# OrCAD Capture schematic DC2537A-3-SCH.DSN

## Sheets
1 PAGE2: size Custom; title: HIGH EFFICIENCY 4 PHASE 120A; rev: 3; company: TM
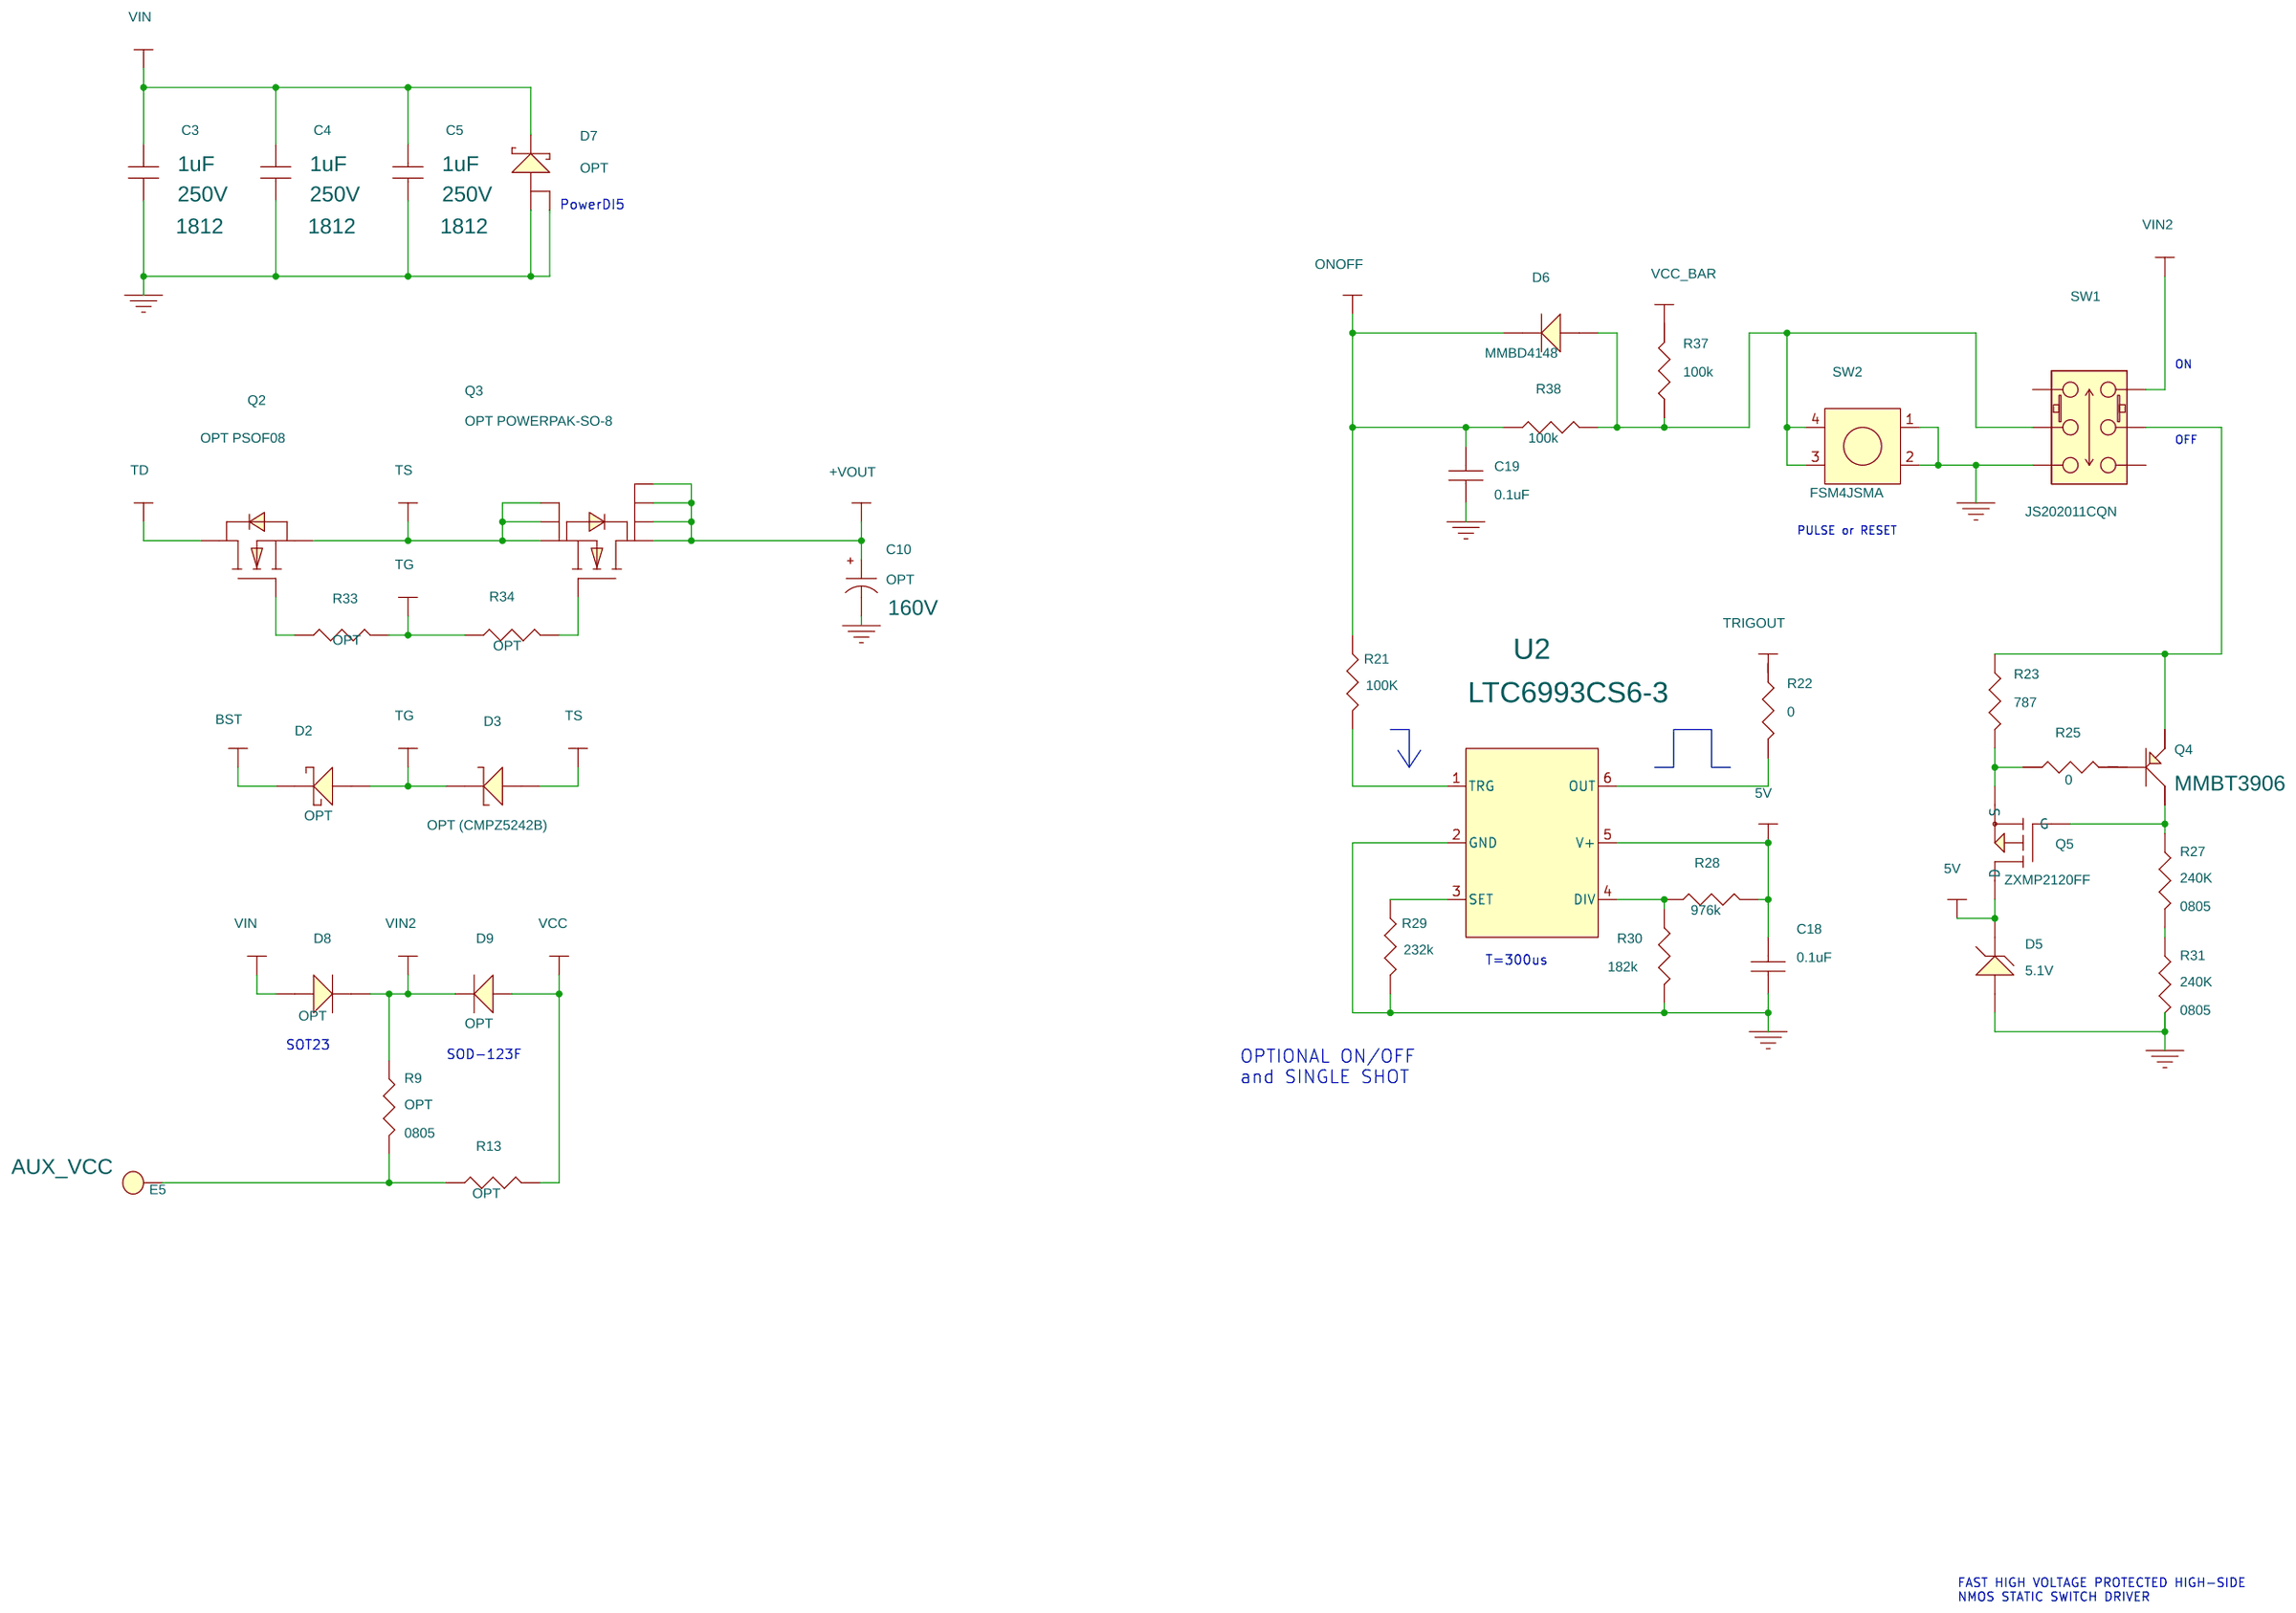
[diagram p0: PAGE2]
2 PAGE1: size Custom
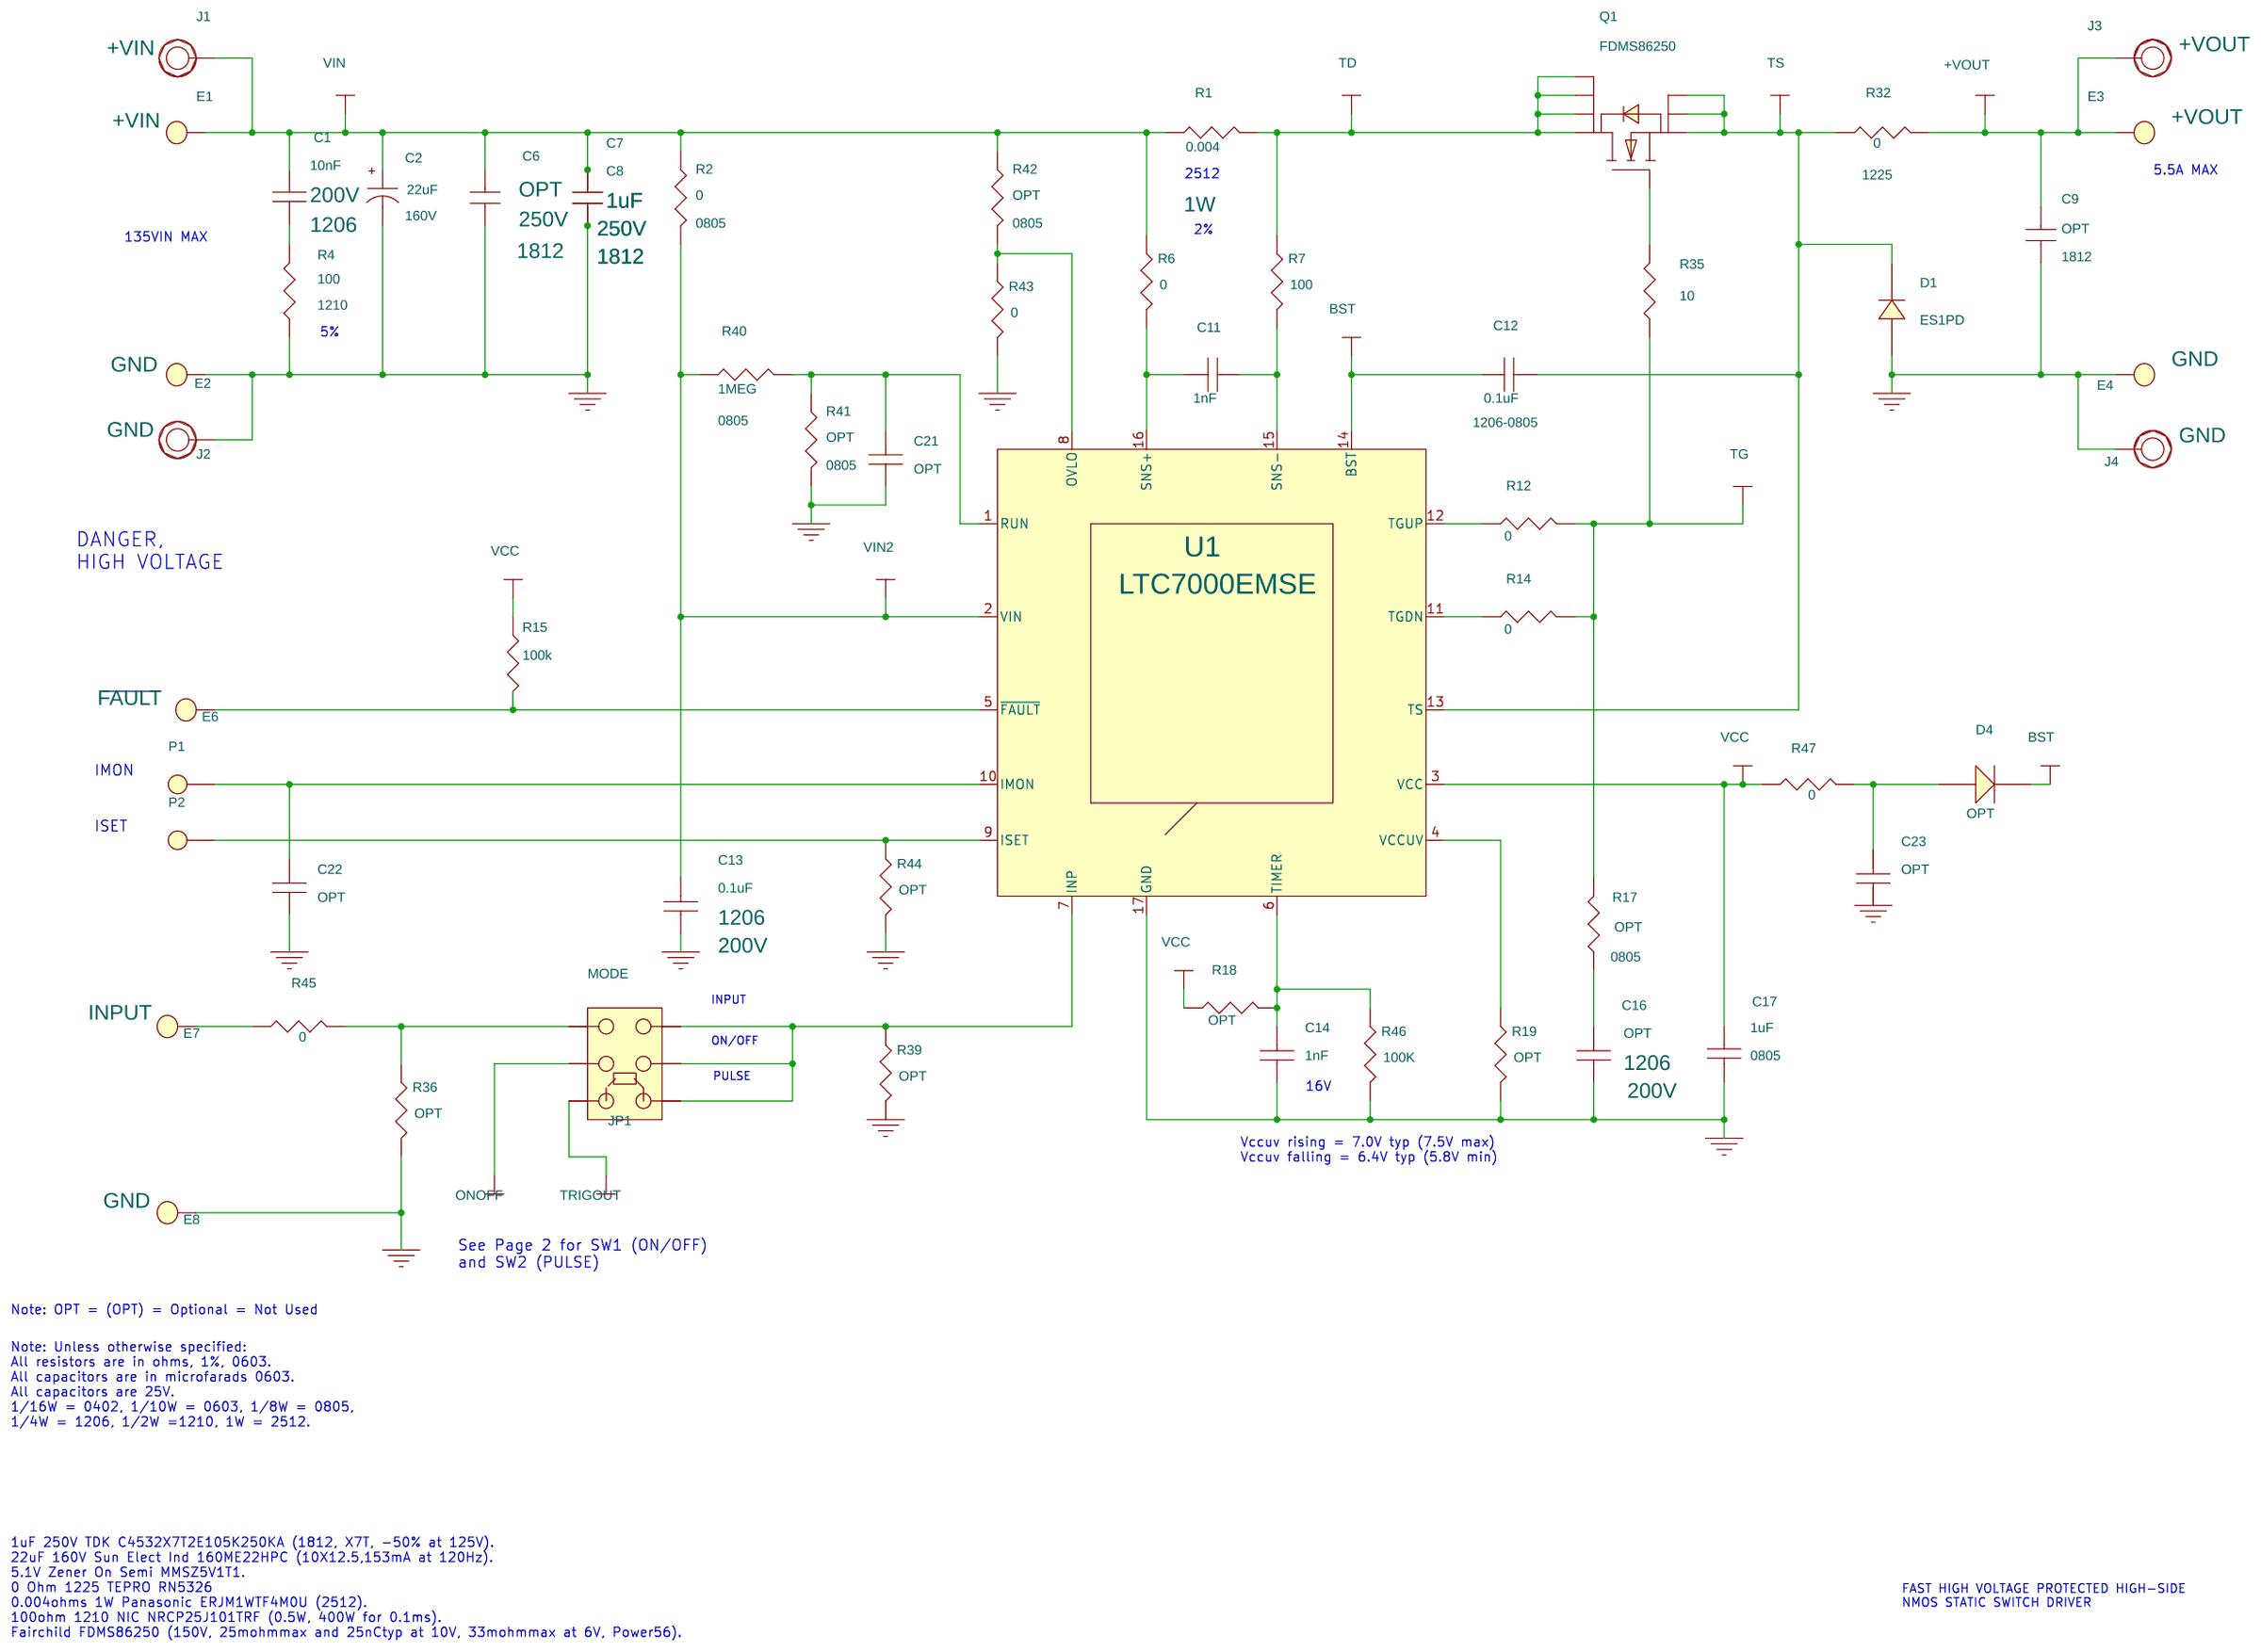
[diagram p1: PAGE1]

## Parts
sheet PAGE1
C1  10nF  [1206]
C2  22uF  [CAP-TH-EE-A-10D]
C6  OPT  [1812]
C7  1uF  [1812]
C8  1uF  [1812]
C9  OPT  [1812]
C11  1nF  [0603]
C12  0.1uF  [1206-0805]
C13  0.1uF  [1206]
C14  1nF  [0603]
C16  OPT  [1206]
C17  1uF  [0805]
C21  OPT  [0603]
C22  OPT  [0603]
C23  OPT  [0603]
D1  ES1PD  [DO-220AA]
D4  OPT  [SOT23]
E1  TURRET  [PAD150-094]
E2  TURRET  [PAD150-094]
E3  TURRET  [PAD150-094]
E4  TURRET  [PAD150-094]
E6  TURRET  [PAD150-094]
E7  TURRET  [PAD150-094]
E8  TURRET  [PAD150-094]
J1  Banana Jack  [KEYSTONE-575-4]
J2  Banana Jack  [KEYSTONE-575-4]
J3  Banana Jack  [KEYSTONE-575-4]
J4  Banana Jack  [KEYSTONE-575-4]
JP1  MODE  [HD2X3-079]
P1  TESTPAD  [PAD060-035]
P2  TESTPAD  [PAD060-035]
Q1  FDMS86250  [POWERPAK-SO-8]
R1  0.004  [2512T]
R2  0  [0805]
R4  100  [1210]
R6  0  [0603]
R7  100  [0603]
R12  0  [0603]
R14  0  [0603]
R15  100k  [0603]
R17  OPT  [0805]
R18  OPT  [0603]
R19  OPT  [0603]
R32  0  [1225]
R35  10  [0603]
R36  OPT  [0603]
R39  OPT  [0603]
R40  1MEG  [0805]
R41  OPT  [0805]
R42  OPT  [0805]
R43  0  [0603]
R44  OPT  [0603]
R45  0  [0603]
R46  100K  [0603]
R47  0  [0603]
U1  LTC7000EMSE  [MSE16]
XJP1  2mm Ctrs.
sheet PAGE2
C3  1uF  [1812]
C4  1uF  [1812]
C5  1uF  [1812]
C10  OPT  [C-10X10.5]
C18  0.1uF  [0603]
C19  0.1uF  [0603]
D2  OPT  [SOT23]
D3  OPT (CMPZ5242B)  [SOT23]
D5  MMSZ5V1T1  [SOD-123]
D6  MMBD4148  [SOT23]
D7  OPT  [POWERDI5]
D8  OPT  [SOT23]
D9  OPT  [SOD-123F]
E5  TURRET  [PAD150-094]
Q2  OPT PSOF08  [PWR-PSOF08A-3P]
Q3  OPT POWERPAK-SO-8  [POWERPAK-SO-8]
Q4  MMBT3906  [SOT23B]
Q5  ZXMP2120FF  [SOT23A]
R9  OPT  [0805]
R13  OPT  [0603]
R21  100K  [0603]
R22  0  [0603]
R23  787  [0603]
R25  0  [0603]
R27  240K  [0805]
R28  976k  [0603]
R29  232k  [0603]
R30  182k  [0603]
R31  240K  [0805]
R33  OPT  [0603]
R34  OPT  [0603]
R37  100k  [0603]
R38  100k  [0603]
SW1  JS202011CQN  [JS202011]
SW2  FSM4JSMA  [SW-FSMJSMA]
U2  LTC6993CS6-3  [TSOT23-6]

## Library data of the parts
C1 C16 = 12061C104KAT2A_0: 1ST PART FIELD: 200V; 2ND PART FIELD: 10%, 0206; 3RD PART FIELD: X7R; 4TH PART FIELD: AVX; 7TH PART FIELD: CAP.
C2 = CAP-HVH-10X10.5: 1ST PART FIELD: 160V; 5TH PART FIELD: 10X20
C3-C6 = CAP1210: 1ST PART FIELD: 250V; 2ND PART FIELD: 20%, 1210; 3RD PART FIELD: X7R; 4TH PART FIELD: TDK; 5TH PART FIELD: 1210; 7TH PART FIELD: CAP.
C7 C8 = CAP1210: 1ST PART FIELD: 250V; 2ND PART FIELD: 20%, 1210; 3RD PART FIELD: X7R; 4TH PART FIELD: TDK; 5TH PART FIELD: 1210; 7TH PART FIELD: CAP.; VOLTAGE: 250V
C9 = CAP1210: 1ST PART FIELD: 100V; 2ND PART FIELD: 20%, 1210; 3RD PART FIELD: X7R; 4TH PART FIELD: TDK; 5TH PART FIELD: 1210; 7TH PART FIELD: CAP.
C11 C14 C18 C19 C21-C23 = 12061C104KAT2A_0: 1ST PART FIELD: 25V; 2ND PART FIELD: 10%, 0603; 3RD PART FIELD: NPO; 4TH PART FIELD: AVX; 5TH PART FIELD: 06033A471KAT2A; 7TH PART FIELD: CAP.
C12 = 12061C104KAT2A_0: 1ST PART FIELD: 25V; 2ND PART FIELD: 10%, 0805; 3RD PART FIELD: X7R; 4TH PART FIELD: AVX; 5TH PART FIELD: 0805; 7TH PART FIELD: CAP.
C13 = 12061C104KAT2A_0: 1ST PART FIELD: 200V; 2ND PART FIELD: 10%, 0206; 3RD PART FIELD: X7R; 4TH PART FIELD: AVX; 7TH PART FIELD: CAP.; VOLTAGE: 200V
C17 = TMK316BJ105KL: 1ST PART FIELD: 16V; 2ND PART FIELD: 10%, 0805; 3RD PART FIELD: X7R; 4TH PART FIELD: TAIYO TUDEN; 7TH PART FIELD: CAP.
D1 = DIODE_8
D4 D8 = CMPSH1-4_14_v2
E1 = TURRET_2501-2: 7TH PART FIELD: HOLE,; 9TH PART FIELD: +VIN
E2 E4 = TURRET_2501-2: 7TH PART FIELD: HOLE,; 9TH PART FIELD: GND
E3 = TURRET_2501-2: 7TH PART FIELD: HOLE,; 9TH PART FIELD: +VOUT
E6 = TURRET_2501-2: 9TH PART FIELD: FAULT
E7 = TURRET_2501-2: 9TH PART FIELD: INPUT
E8 = TURRET_2501-2: 9TH PART FIELD: GND
J1 = E-KEY-575_0: 9th Part Field: +VIN
J2 J4 = E-KEY-575_0: 9th Part Field: GND
J3 = E-KEY-575_0: 9th Part Field: +VOUT
JP1 = hdr2X4_0: HEADER, 4PIN, DBL ROW 2mm; Part Number: SAMTEC TMM-104-02-L-D
P1 = P-TP_2
P2 = P-TP_3
Q1 Q3 = SI7456DP: 1ST PART FIELD: 150V; 2ND PART FIELD: POWERPAK SO-8; 3RD PART FIELD: N-CHANNEL; 5TH PART FIELD: Si7450DP; 7TH PART FIELD: FET; opt: *
R1 = AAC-0805: 1ST PART FIELD: 1W; 2ND PART FIELD: 1%, 0805; 5TH PART FIELD: 1206; 7TH PART FIELD: RES.
R2 R9 R17 R27 R31 R40-R42 = AAC-0805: 2ND PART FIELD: 1%, 0805; 7TH PART FIELD: RES.
R4 = AAC-0805: 1ST PART FIELD: 0.5W; 2ND PART FIELD: 5%, 1210; 4TH PART FIELD: NIC; 5TH PART FIELD: NRCP25J101TRF; 7TH PART FIELD: RES.
R6 R7 R12-R15 R18 R19 R21-R23 R25 R28-R30 R33-R39 R43-R47 = AAC-0805: 1ST PART FIELD: 1/16W; 2ND PART FIELD: 1%, 0603; 5TH PART FIELD: CR16-xxxxFM; 7TH PART FIELD: RES.
R32 = AAC-0805: 1ST PART FIELD: 1/2W; 2ND PART FIELD: 1%, 1210; 5TH PART FIELD: 1210; 7TH PART FIELD: RES.
U1 = LT1339_64: 3RD PART FIELD: ANALOG; 4TH PART FIELD: LINEAR TECH.; 5TH PART FIELD: LTC7000EMS16E; 7TH PART FIELD: I.C.
XJP1 = Samtec_2SN-BK-G: SHUNT; Part Number: SAMTEC 2SN-BK-G
C10 = CAP-HVH-10X10.5: 1ST PART FIELD: 160V; 5TH PART FIELD: 10X10.5
D2 = CMPSH1-4_12
D3 = CMPSH1-4_16
D5 = MMBZ5248BLT1_0: 1ST PART FIELD: 5.1V; 2ND PART FIELD: 5%, SOD123; 3RD PART FIELD: ZENER; 4TH PART FIELD: DIODES INC.; 7TH PART FIELD: DIODE
D6 = CMPSH1-4_11
D7 = DIODE-PDS3100
D9 = DIODE-CMMR1U-SOD123F
E5 = TURRET_2501-2: 9TH PART FIELD: AUX_VCC
Q2 = SI7456DP_3: 1ST PART FIELD: 150V; 2ND PART FIELD: POWERPAK SO-8; 3RD PART FIELD: N-CHANNEL; 5TH PART FIELD: Si7450DP; 7TH PART FIELD: FET; opt: *
Q4 = MMBT3906LT1_0: 2ND PART FIELD: SOT23; 3RD PART FIELD: PNP; 4TH PART FIELD: ZETEX; 5TH PART FIELD: FMMT718; 7TH PART FIELD: XSTR.
Q5 = MOSFET_P-DIODE_2
SW1 = SW_5: HEADER, 4PIN, DBL ROW 2mm
SW2 = BUTTON_0
U2 = LTC2400_2

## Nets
5V: C18.1 D5.1 Q5.D R28.2 R37.1 U2.5(V+)
GND: C2.2 C3.2 C4.2 C5.2 C6.2 C7.2 C8.2 C9.2 C10.2 C13.2 C14.2 C16.2 C17.2 C18.2 C19.2 C21.2 C22.2 C23.2 D1.2(K) D5.2 D7.2 D7.3 E2.1 E4.1 E8.1 J2.1 J4.1 R4.2 R19.2 R29.2 R30.2 R31.1 R36.2 R39.2 R41.1 R43.2 R44.2 R46.2 SW1.6 SW2.1 SW2.2 U1.17(GND) U2.2(GND)
VCC: C17.1 D9.2 R13.2 R15.1 R18.1 R47.1 U1.3(VCC)
VIN: C1.2 C2.1 C3.1 C4.1 C5.1 C6.1 C7.1 C8.1 D7.1 D8.1(A) E1.1 J1.1 R1.2 R2.2 R6.1 R42.2
VIN2: C13.1 D8.3(K) D9.1 R2.1 R9.2 R40.2 SW1.1 U1.2(VIN)
+VOUT: C9.1 C10.1 E3.1 J3.1 Q3.5 Q3.6 Q3.7 Q3.8 R32.1
BST: C12.2 D2.3(K) D4.3(K) U1.14(BST)
ONOFF: C19.1 D6.3(K) JP1.4 R21.1 R38.2
TD: Q1.5 Q1.6 Q1.7 Q1.8 Q2.D R1.1 R7.1
TG: D2.1(A) D3.3(K) R12.2 R14.2 R17.1 R33.2 R34.1 R35.1
TRIGOUT: JP1.6 R22.1
TS: C12.1 D1.1(A) D3.1(A) Q1.1 Q1.2 Q1.3 Q2.S Q3.1 Q3.2 Q3.3 R32.2 U1.13(TS)
N19054060: E6.1 R15.2 U1.5(~{FAULT})
N19054068: C14.1 R18.2 R46.1 U1.6(TIMER)
N19054097: C22.1 P1.1(A) U1.10(IMON)
N19054138: C21.1 R40.1 R41.2 U1.1(RUN)
N19054192: C16.1 R17.2
N19054262: R42.1 R43.1 U1.8(OVLO)
N19054491: Q1.4 R35.2
N19054777: P2.1(A) R44.1 U1.9(ISET)
N19054844: C11.2 R7.2 U1.15(SNS-)
N19054856: C1.1 R4.1
N19054862: R12.1 U1.12(TGUP)
N19054913: C11.1 R6.2 U1.16(SNS+)
N19054937: R14.1 U1.11(TGDN)
N19056424: E5.1 R9.1 R13.1
N19056950: Q3.4 R34.2
N19056982: Q2.G R33.1
N19060184: JP1.2 R36.1 R45.2
N19060223: JP1.1 JP1.3 JP1.5 R39.1 U1.7(INP)
N19061333: E7.1 R45.1
N19061526: R19.1 U1.4(VCCUV)
N19068396: R28.1 R30.1 U2.4(DIV)
N19068478: D6.1(A) R37.2 R38.1 SW1.5 SW2.3 SW2.4
N19068494: Q4.E R23.1 SW1.2
N19068588: R21.2 U2.1(TRG)
N19068610: R27.1 R31.2
N19068630: R22.2 U2.6(OUT)
N19068638: Q5.S R23.2 R25.2
N19068729: Q4.C Q5.G R27.2
N19068794: R29.1 U2.3(SET)
N19068796: Q4.B R25.1
N19081929: C23.1 D4.1(A) R47.2

Not connected (* = marked no-connect by the designer): SW1 3 4

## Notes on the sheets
sheet 1
- PowerDI5
- ON
- OFF
- PULSE or RESET
- T=300us
- SOT23
- SOD-123F
- OPTIONAL ON/OFF
  and SINGLE SHOT
- FAST HIGH VOLTAGE PROTECTED HIGH-SIDE
  NMOS STATIC SWITCH DRIVER
sheet 2
- 2512
- 5.5A MAX
- 135VIN MAX
- 2%
- 5%
- DANGER,
  HIGH VOLTAGE
- IMON
- ISET
- INPUT
- ON/OFF
- PULSE
- 16V
- Vccuv rising = 7.0V typ (7.5V max)
  Vccuv falling = 6.4V typ (5.8V min)
- See Page 2 for SW1 (ON/OFF)
  and SW2 (PULSE)
- Note: OPT = (OPT) = Optional = Not Used
- Note: Unless otherwise specified:
  All resistors are in ohms, 1%, 0603.
  All capacitors are in microfarads 0603.
  All capacitors are 25V.
  1/16W = 0402, 1/10W = 0603, 1/8W = 0805,
  1/4W = 1206, 1/2W =1210, 1W = 2512.
- 1uF 250V TDK C4532X7T2E105K250KA (1812, X7T, -50% at 125V).
  22uF 160V Sun Elect Ind 160ME22HPC (10X12.5,153mA at 120Hz).
  5.1V Zener On Semi MMSZ5V1T1.
  0 Ohm 1225 TEPRO RN5326
  0.004ohms 1W Panasonic ERJM1WTF4M0U (2512).
  100ohm 1210 NIC NRCP25J101TRF (0.5W, 400W for 0.1ms).
  Fairchild FDMS86250 (150V, 25mohmmax and 25nCtyp at 10V, 33mohmmax at 6V, Power56).
- FAST HIGH VOLTAGE PROTECTED HIGH-SIDE
  NMOS STATIC SWITCH DRIVER
